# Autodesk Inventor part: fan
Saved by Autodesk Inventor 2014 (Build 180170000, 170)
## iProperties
Created: 2015-06
Part Number: fan
Material: Generic
Document SubType Name: Modeling
Designer: common
Density: 1 g/cm^3
Appearance: Default
Author: common
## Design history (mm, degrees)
node "fan.ipt1"
body "Solid1"
node "Base1"
